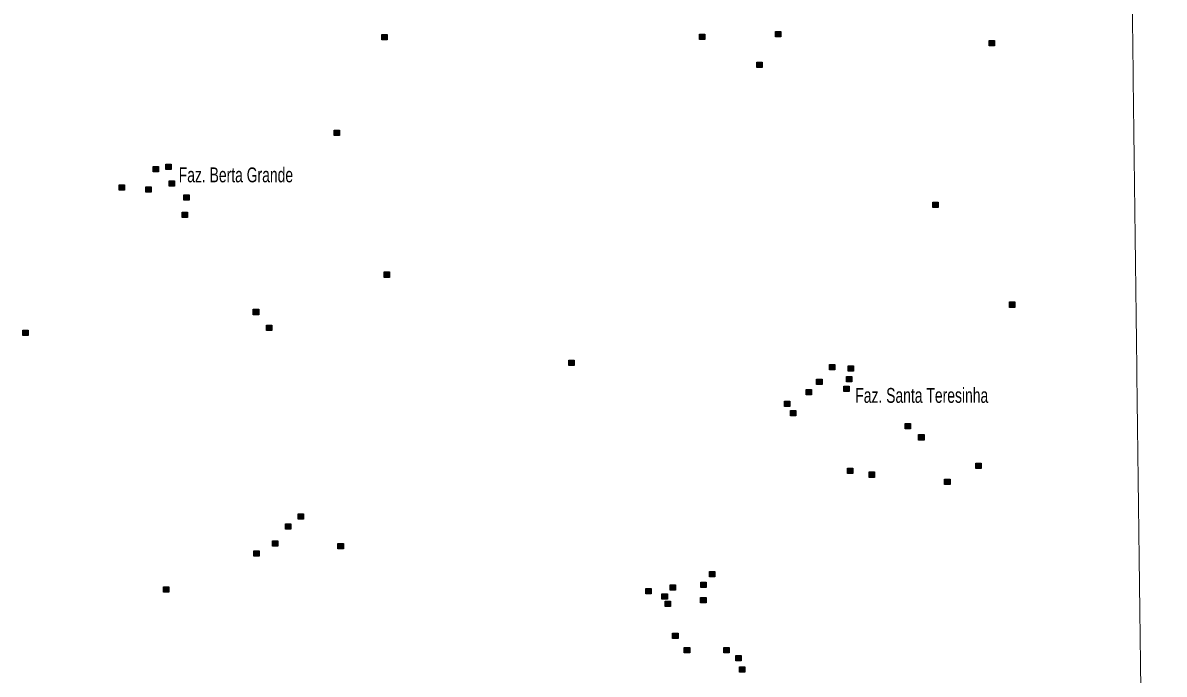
# Model space of a CAD drawing. Extents: x 265.7 to 292.1, y 7676.2 to 7704.2.
# Drawn here: x 285.96 to 292.1, y 7686.68 to 7690.19 of the extents above; entities that cross this region are included whole.
import ezdxf

# ---------------------------------------------------------------- set-up
doc = ezdxf.new("R2010")
doc.units = 0
doc.header["$LTSCALE"] = 0.032
doc.layers.add('2', color=7, linetype='Continuous', lineweight=25)
doc.layers.add('63', color=7, linetype='Continuous', lineweight=13)
doc.layers.add('61', color=7, linetype='Continuous')

msp = doc.modelspace()

# ---------------------------------------------------------------- hatches: boundary and pattern name
at = {"layer": '2'}
for points in [[(290.0086, 7690.144), (290.0376, 7690.144), (290.0376, 7690.115), (290.0086, 7690.115)], [(287.8893, 7690.1287), (287.9183, 7690.1287), (287.9183, 7690.0997), (287.8893, 7690.0997)], [(289.6002, 7690.1303), (289.6292, 7690.1303), (289.6292, 7690.1013), (289.6002, 7690.1013)], [(291.1603, 7690.0956), (291.1893, 7690.0956), (291.1893, 7690.0666), (291.1603, 7690.0666)], [(289.9079, 7689.9798), (289.9369, 7689.9798), (289.9369, 7689.9508), (289.9079, 7689.9508)], [(287.6318, 7689.6138), (287.6608, 7689.6138), (287.6608, 7689.5848), (287.6318, 7689.5848)], [(286.6576, 7689.4177), (286.6866, 7689.4177), (286.6866, 7689.3887), (286.6576, 7689.3887)], [(286.7262, 7689.4305), (286.7552, 7689.4305), (286.7552, 7689.4015), (286.7262, 7689.4015)], [(286.7433, 7689.341), (286.7723, 7689.341), (286.7723, 7689.312), (286.7433, 7689.312)], [(286.4745, 7689.3192), (286.5035, 7689.3192), (286.5035, 7689.2902), (286.4745, 7689.2902)], [(286.6172, 7689.3086), (286.6462, 7689.3086), (286.6462, 7689.2796), (286.6172, 7689.2796)], [(286.8223, 7689.2644), (286.8513, 7689.2644), (286.8513, 7689.2354), (286.8223, 7689.2354)], [(290.8567, 7689.2256), (290.8857, 7689.2256), (290.8857, 7689.1966), (290.8567, 7689.1966)], [(286.8143, 7689.1723), (286.8433, 7689.1723), (286.8433, 7689.1433), (286.8143, 7689.1433)], [(287.9013, 7688.8495), (287.9303, 7688.8495), (287.9303, 7688.8205), (287.9013, 7688.8205)], [(291.2684, 7688.6881), (291.2974, 7688.6881), (291.2974, 7688.6591), (291.2684, 7688.6591)], [(287.1968, 7688.6485), (287.2258, 7688.6485), (287.2258, 7688.6195), (287.1968, 7688.6195)], [(285.9556, 7688.5372), (285.9846, 7688.5372), (285.9846, 7688.5082), (285.9556, 7688.5082)], [(287.2678, 7688.5638), (287.2968, 7688.5638), (287.2968, 7688.5348), (287.2678, 7688.5348)], [(288.8956, 7688.3749), (288.9246, 7688.3749), (288.9246, 7688.3459), (288.8956, 7688.3459)], [(290.2999, 7688.3524), (290.3289, 7688.3524), (290.3289, 7688.3234), (290.2999, 7688.3234)], [(290.4, 7688.345), (290.429, 7688.345), (290.429, 7688.316), (290.4, 7688.316)], [(290.2305, 7688.2732), (290.2595, 7688.2732), (290.2595, 7688.2442), (290.2305, 7688.2442)], [(290.3774, 7688.2353), (290.4064, 7688.2353), (290.4064, 7688.2063), (290.3774, 7688.2063)], [(290.3911, 7688.2869), (290.4201, 7688.2869), (290.4201, 7688.2579), (290.3911, 7688.2579)], [(290.1747, 7688.2175), (290.2037, 7688.2175), (290.2037, 7688.1885), (290.1747, 7688.1885)], [(290.0577, 7688.1537), (290.0867, 7688.1537), (290.0867, 7688.1247), (290.0577, 7688.1247)], [(290.0892, 7688.1038), (290.1182, 7688.1038), (290.1182, 7688.0748), (290.0892, 7688.0748)], [(290.7066, 7688.0336), (290.7356, 7688.0336), (290.7356, 7688.0046), (290.7066, 7688.0046)], [(290.7798, 7687.974), (290.8088, 7687.974), (290.8088, 7687.945), (290.7798, 7687.945)], [(291.0884, 7687.8213), (291.1174, 7687.8213), (291.1174, 7687.7923), (291.0884, 7687.7923)], [(290.3959, 7687.793), (290.4249, 7687.793), (290.4249, 7687.764), (290.3959, 7687.764)], [(290.513, 7687.7729), (290.542, 7687.7729), (290.542, 7687.7439), (290.513, 7687.7439)], [(290.9198, 7687.7349), (290.9488, 7687.7349), (290.9488, 7687.7059), (290.9198, 7687.7059)], [(287.3703, 7687.4936), (287.3993, 7687.4936), (287.3993, 7687.4646), (287.3703, 7687.4646)], [(287.4389, 7687.5485), (287.4679, 7687.5485), (287.4679, 7687.5195), (287.4389, 7687.5195)], [(287.2993, 7687.4032), (287.3283, 7687.4032), (287.3283, 7687.3742), (287.2993, 7687.3742)], [(287.6528, 7687.3887), (287.6818, 7687.3887), (287.6818, 7687.3597), (287.6528, 7687.3597)], [(287.2, 7687.3484), (287.229, 7687.3484), (287.229, 7687.3194), (287.2, 7687.3194)], [(289.6535, 7687.2378), (289.6825, 7687.2378), (289.6825, 7687.2088), (289.6535, 7687.2088)], [(286.7133, 7687.1555), (286.7423, 7687.1555), (286.7423, 7687.1265), (286.7133, 7687.1265)], [(289.3104, 7687.1458), (289.3394, 7687.1458), (289.3394, 7687.1168), (289.3104, 7687.1168)], [(289.4411, 7687.166), (289.4701, 7687.166), (289.4701, 7687.137), (289.4411, 7687.137)], [(289.6065, 7687.1805), (289.6355, 7687.1805), (289.6355, 7687.1515), (289.6065, 7687.1515)], [(289.3976, 7687.1175), (289.4266, 7687.1175), (289.4266, 7687.0885), (289.3976, 7687.0885)], [(289.4153, 7687.0772), (289.4443, 7687.0772), (289.4443, 7687.0482), (289.4153, 7687.0482)], [(289.6059, 7687.0982), (289.6349, 7687.0982), (289.6349, 7687.0692), (289.6059, 7687.0692)], [(289.455, 7686.9061), (289.484, 7686.9061), (289.484, 7686.8771), (289.455, 7686.8771)], [(289.5178, 7686.8286), (289.5468, 7686.8286), (289.5468, 7686.7996), (289.5178, 7686.7996)], [(289.7301, 7686.8286), (289.7591, 7686.8286), (289.7591, 7686.7996), (289.7301, 7686.7996)], [(289.7947, 7686.785), (289.8237, 7686.785), (289.8237, 7686.756), (289.7947, 7686.756)], [(289.8156, 7686.7246), (289.8446, 7686.7246), (289.8446, 7686.6956), (289.8156, 7686.6956)]]:
    msp.add_hatch(color=256, dxfattribs=at).paths.add_polyline_path(points)

# ---------------------------------------------------------------- linework, layer by layer
for points in [[(290.0086, 7690.144), (290.0376, 7690.144), (290.0376, 7690.115), (290.0086, 7690.115)], [(287.8893, 7690.1287), (287.9183, 7690.1287), (287.9183, 7690.0997), (287.8893, 7690.0997)], [(289.6002, 7690.1303), (289.6292, 7690.1303), (289.6292, 7690.1013), (289.6002, 7690.1013)], [(291.1603, 7690.0956), (291.1893, 7690.0956), (291.1893, 7690.0666), (291.1603, 7690.0666)], [(289.9079, 7689.9798), (289.9369, 7689.9798), (289.9369, 7689.9508), (289.9079, 7689.9508)], [(287.6318, 7689.6138), (287.6608, 7689.6138), (287.6608, 7689.5848), (287.6318, 7689.5848)], [(286.6576, 7689.4177), (286.6866, 7689.4177), (286.6866, 7689.3887), (286.6576, 7689.3887)], [(286.7262, 7689.4305), (286.7552, 7689.4305), (286.7552, 7689.4015), (286.7262, 7689.4015)], [(286.7433, 7689.341), (286.7723, 7689.341), (286.7723, 7689.312), (286.7433, 7689.312)], [(286.4745, 7689.3192), (286.5035, 7689.3192), (286.5035, 7689.2902), (286.4745, 7689.2902)], [(286.6172, 7689.3086), (286.6462, 7689.3086), (286.6462, 7689.2796), (286.6172, 7689.2796)], [(286.8223, 7689.2644), (286.8513, 7689.2644), (286.8513, 7689.2354), (286.8223, 7689.2354)], [(290.8567, 7689.2256), (290.8857, 7689.2256), (290.8857, 7689.1966), (290.8567, 7689.1966)], [(286.8143, 7689.1723), (286.8433, 7689.1723), (286.8433, 7689.1433), (286.8143, 7689.1433)], [(287.9013, 7688.8495), (287.9303, 7688.8495), (287.9303, 7688.8205), (287.9013, 7688.8205)], [(291.2684, 7688.6881), (291.2974, 7688.6881), (291.2974, 7688.6591), (291.2684, 7688.6591)], [(287.1968, 7688.6485), (287.2258, 7688.6485), (287.2258, 7688.6195), (287.1968, 7688.6195)], [(285.9556, 7688.5372), (285.9846, 7688.5372), (285.9846, 7688.5082), (285.9556, 7688.5082)], [(287.2678, 7688.5638), (287.2968, 7688.5638), (287.2968, 7688.5348), (287.2678, 7688.5348)], [(288.8956, 7688.3749), (288.9246, 7688.3749), (288.9246, 7688.3459), (288.8956, 7688.3459)], [(290.2999, 7688.3524), (290.3289, 7688.3524), (290.3289, 7688.3234), (290.2999, 7688.3234)], [(290.4, 7688.345), (290.429, 7688.345), (290.429, 7688.316), (290.4, 7688.316)], [(290.2305, 7688.2732), (290.2595, 7688.2732), (290.2595, 7688.2442), (290.2305, 7688.2442)], [(290.3774, 7688.2353), (290.4064, 7688.2353), (290.4064, 7688.2063), (290.3774, 7688.2063)], [(290.3911, 7688.2869), (290.4201, 7688.2869), (290.4201, 7688.2579), (290.3911, 7688.2579)], [(290.1747, 7688.2175), (290.2037, 7688.2175), (290.2037, 7688.1885), (290.1747, 7688.1885)], [(290.0577, 7688.1537), (290.0867, 7688.1537), (290.0867, 7688.1247), (290.0577, 7688.1247)], [(290.0892, 7688.1038), (290.1182, 7688.1038), (290.1182, 7688.0748), (290.0892, 7688.0748)], [(290.7066, 7688.0336), (290.7356, 7688.0336), (290.7356, 7688.0046), (290.7066, 7688.0046)], [(290.7798, 7687.974), (290.8088, 7687.974), (290.8088, 7687.945), (290.7798, 7687.945)], [(291.0884, 7687.8213), (291.1174, 7687.8213), (291.1174, 7687.7923), (291.0884, 7687.7923)], [(290.3959, 7687.793), (290.4249, 7687.793), (290.4249, 7687.764), (290.3959, 7687.764)], [(290.513, 7687.7729), (290.542, 7687.7729), (290.542, 7687.7439), (290.513, 7687.7439)], [(290.9198, 7687.7349), (290.9488, 7687.7349), (290.9488, 7687.7059), (290.9198, 7687.7059)], [(287.3703, 7687.4936), (287.3993, 7687.4936), (287.3993, 7687.4646), (287.3703, 7687.4646)], [(287.4389, 7687.5485), (287.4679, 7687.5485), (287.4679, 7687.5195), (287.4389, 7687.5195)], [(287.2993, 7687.4032), (287.3283, 7687.4032), (287.3283, 7687.3742), (287.2993, 7687.3742)], [(287.6528, 7687.3887), (287.6818, 7687.3887), (287.6818, 7687.3597), (287.6528, 7687.3597)], [(287.2, 7687.3484), (287.229, 7687.3484), (287.229, 7687.3194), (287.2, 7687.3194)], [(289.6535, 7687.2378), (289.6825, 7687.2378), (289.6825, 7687.2088), (289.6535, 7687.2088)], [(286.7133, 7687.1555), (286.7423, 7687.1555), (286.7423, 7687.1265), (286.7133, 7687.1265)], [(289.3104, 7687.1458), (289.3394, 7687.1458), (289.3394, 7687.1168), (289.3104, 7687.1168)], [(289.4411, 7687.166), (289.4701, 7687.166), (289.4701, 7687.137), (289.4411, 7687.137)], [(289.6065, 7687.1805), (289.6355, 7687.1805), (289.6355, 7687.1515), (289.6065, 7687.1515)], [(289.3976, 7687.1175), (289.4266, 7687.1175), (289.4266, 7687.0885), (289.3976, 7687.0885)], [(289.4153, 7687.0772), (289.4443, 7687.0772), (289.4443, 7687.0482), (289.4153, 7687.0482)], [(289.6059, 7687.0982), (289.6349, 7687.0982), (289.6349, 7687.0692), (289.6059, 7687.0692)], [(289.455, 7686.9061), (289.484, 7686.9061), (289.484, 7686.8771), (289.455, 7686.8771)], [(289.5178, 7686.8286), (289.5468, 7686.8286), (289.5468, 7686.7996), (289.5178, 7686.7996)], [(289.7301, 7686.8286), (289.7591, 7686.8286), (289.7591, 7686.7996), (289.7301, 7686.7996)], [(289.7947, 7686.785), (289.8237, 7686.785), (289.8237, 7686.756), (289.7947, 7686.756)], [(289.8156, 7686.7246), (289.8446, 7686.7246), (289.8446, 7686.6956), (289.8156, 7686.6956)]]:
    msp.add_lwpolyline(points, close=True, dxfattribs=at)
at = {"layer": '63'}
msp.add_spline([(292.1022, 7676.5221), (292.0951, 7677.087), (292.088, 7677.6519), (292.081, 7678.2168), (292.0739, 7678.7818), (292.0668, 7679.3467), (292.0598, 7679.9116), (292.0527, 7680.4765), (292.0457, 7681.0414), (292.0386, 7681.6064), (292.0316, 7682.1713), (292.0245, 7682.7362), (292.0175, 7683.3011), (292.0104, 7683.866), (292.0034, 7684.431), (291.9963, 7684.9959), (291.9893, 7685.5608), (291.9822, 7686.1257), (291.9752, 7686.6906), (291.9681, 7687.2556), (291.9611, 7687.8205), (291.9541, 7688.3854), (291.947, 7688.9503), (291.94, 7689.5152), (291.933, 7690.0801), (291.9259, 7690.6451), (291.9189, 7691.21), (291.9119, 7691.7749), (291.9049, 7692.3398), (291.8978, 7692.9047), (291.8908, 7693.4696), (291.8838, 7694.0345), (291.8768, 7694.5995), (291.8698, 7695.1644), (291.8628, 7695.7293), (291.8557, 7696.2942), (291.8487, 7696.8591), (291.8417, 7697.424), (291.8347, 7697.9889), (291.8277, 7698.5539), (291.8207, 7699.1188), (291.8137, 7699.6837), (291.8067, 7700.2486), (291.7997, 7700.8135), (291.7927, 7701.3784), (291.7857, 7701.9433), (291.7787, 7702.5082), (291.7717, 7703.0731), (291.7647, 7703.638), (291.7577, 7704.203)], degree=3, dxfattribs=at)

# ---------------------------------------------------------------- texts
at = {"layer": '61', "width": 0.7}
for s, p in [('Faz. Berta Grande', (286.7951, 7689.3322)), ('Faz. Santa Teresinha', (290.4387, 7688.1453))]:
    msp.add_text(s, height=0.08, dxfattribs=at).set_placement(p)

doc.saveas('drawing.dxf')
